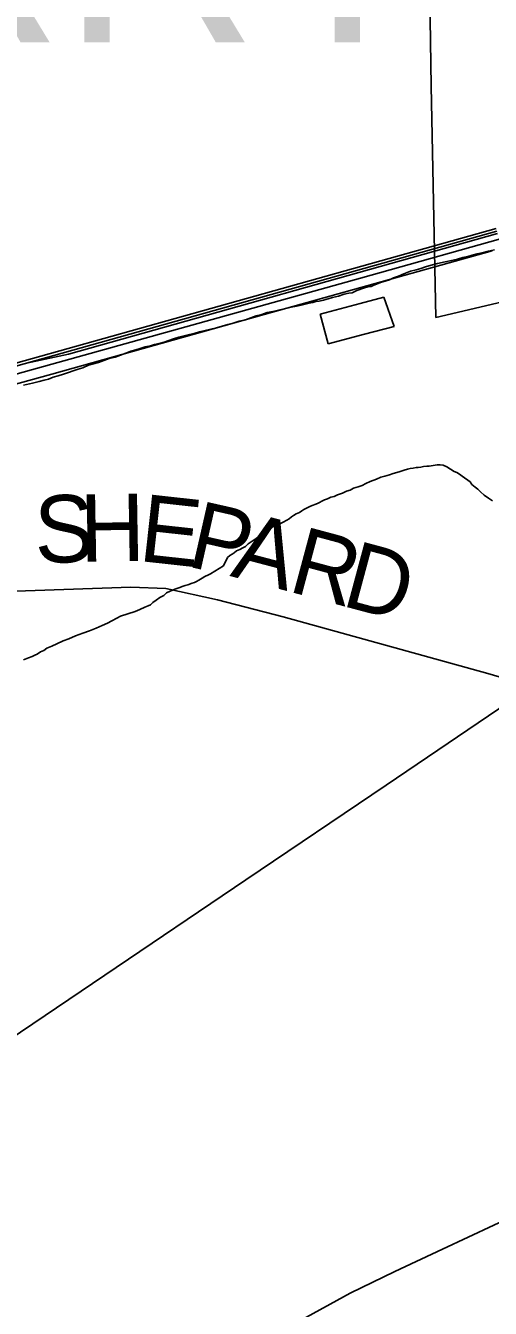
# Model space of a CAD drawing. Extents: x -59 to 82, y -3 to 49.
# Drawn here: x -49.098 to -48.706, y 47.357 to 48.44 of the extents above; entities that cross this region are included whole.
import ezdxf

# ---------------------------------------------------------------- set-up
doc = ezdxf.new("R2010")
doc.units = 0
for name, color, linetype in [('GM_X_Corporation', 7, 'Continuous'), ('GM_X_Minor_Lake', 7, 'Continuous'), ('GM_X_Minor_River', 7, 'Continuous'), ('GM_X_Rail_Line', 7, 'Continuous'), ('GM_X_State_Route', 7, 'Continuous'), ('GM_X_Township_Road', 7, 'Continuous'), ('GM_X_Township_Road_Text', 7, 'Continuous'), ('GM_X_Township_Text', 7, 'Continuous')]:
    doc.layers.add(name, color=color, linetype=linetype)

msp = doc.modelspace()

# ---------------------------------------------------------------- linework, layer by layer
at = {"layer": 'GM_X_Corporation'}
for p, q in [((-48.7611, 48.7525), (-48.7557, 48.3888)), ((-48.7557, 48.3888), (-48.7519, 48.1936)), ((-48.7519, 48.1936), (-48.3129, 48.2967))]:
    msp.add_line(p, q, dxfattribs=at)
at = {"layer": 'GM_X_Minor_Lake'}
for p, q in [((-48.8158, 48.2054), (-48.8494, 48.1964)), ((-48.8494, 48.1964), (-48.8158, 48.2054)), ((-48.7956, 48.2108), (-48.8158, 48.2054)), ((-48.787, 48.1859), (-48.7956, 48.2108)), ((-48.8494, 48.1964), (-48.8428, 48.1714)), ((-48.8428, 48.1714), (-48.8494, 48.1964)), ((-48.8121, 48.1794), (-48.787, 48.1859)), ((-48.8428, 48.1714), (-48.8121, 48.1794)), ((-48.8121, 48.1794), (-48.8428, 48.1714))]:
    msp.add_line(p, q, dxfattribs=at)
at = {"layer": 'GM_X_Minor_River'}
for p, q in [((-48.725, 48.2449), (-48.7212, 48.2462)), ((-48.7212, 48.2462), (-48.717, 48.2474)), ((-48.717, 48.2474), (-48.7129, 48.2482)), ((-48.7129, 48.2482), (-48.7076, 48.2495)), ((-48.7076, 48.2495), (-48.7023, 48.2507)), ((-48.7686, 48.2338), (-48.7644, 48.235)), ((-48.7644, 48.235), (-48.7606, 48.2362)), ((-48.7606, 48.2362), (-48.7557, 48.2378)), ((-48.7557, 48.2378), (-48.7504, 48.2391)), ((-48.7504, 48.2391), (-48.744, 48.2404)), ((-48.744, 48.2404), (-48.7386, 48.2416)), ((-48.7386, 48.2416), (-48.7337, 48.2429)), ((-48.7337, 48.2429), (-48.7292, 48.2441)), ((-48.7292, 48.2441), (-48.725, 48.2449)), ((-48.7977, 48.2233), (-48.7947, 48.2241)), ((-48.7947, 48.2241), (-48.7909, 48.2253)), ((-48.7909, 48.2253), (-48.7875, 48.2269)), ((-48.7875, 48.2269), (-48.7833, 48.2285)), ((-48.7833, 48.2285), (-48.7788, 48.2305)), ((-48.7788, 48.2305), (-48.7731, 48.2325)), ((-48.7731, 48.2325), (-48.7686, 48.2338)), ((-48.8341, 48.2115), (-48.8291, 48.2132)), ((-48.8291, 48.2132), (-48.8253, 48.214)), ((-48.8253, 48.214), (-48.8223, 48.2144)), ((-48.8223, 48.2144), (-48.8185, 48.2164)), ((-48.8185, 48.2164), (-48.8129, 48.2184)), ((-48.8129, 48.2184), (-48.8083, 48.2197)), ((-48.8083, 48.2197), (-48.8064, 48.2197)), ((-48.8064, 48.2197), (-48.8041, 48.2209)), ((-48.8041, 48.2209), (-48.8019, 48.2217)), ((-48.8019, 48.2217), (-48.7977, 48.2233)), ((-48.8784, 48.2011), (-48.8739, 48.2023)), ((-48.8739, 48.2023), (-48.8693, 48.2032)), ((-48.8693, 48.2032), (-48.8655, 48.204)), ((-48.8655, 48.204), (-48.8621, 48.2049)), ((-48.8621, 48.2049), (-48.8587, 48.2057)), ((-48.8587, 48.2057), (-48.8557, 48.2061)), ((-48.8557, 48.2061), (-48.853, 48.207)), ((-48.853, 48.207), (-48.8504, 48.2074)), ((-48.8504, 48.2074), (-48.8466, 48.2082)), ((-48.8466, 48.2082), (-48.8447, 48.2087)), ((-48.8447, 48.2087), (-48.839, 48.2103)), ((-48.839, 48.2103), (-48.8341, 48.2115)), ((-48.9178, 48.1904), (-48.9125, 48.1917)), ((-48.9125, 48.1917), (-48.908, 48.1933)), ((-48.908, 48.1933), (-48.9035, 48.1949)), ((-48.9035, 48.1949), (-48.8985, 48.1961)), ((-48.8985, 48.1961), (-48.894, 48.1978)), ((-48.894, 48.1978), (-48.8879, 48.199)), ((-48.8879, 48.199), (-48.8834, 48.1999)), ((-48.8834, 48.1999), (-48.8784, 48.2011)), ((-48.9557, 48.1801), (-48.9512, 48.1814)), ((-48.9512, 48.1814), (-48.9368, 48.1847)), ((-48.9368, 48.1847), (-48.9322, 48.1863)), ((-48.9322, 48.1863), (-48.9273, 48.1876)), ((-48.9273, 48.1876), (-48.9228, 48.1888)), ((-48.9228, 48.1888), (-48.9178, 48.1904)), ((-48.9925, 48.1695), (-48.9891, 48.1707)), ((-48.9891, 48.1707), (-48.9853, 48.1716)), ((-48.9853, 48.1716), (-48.9811, 48.1728)), ((-48.9811, 48.1728), (-48.977, 48.174)), ((-48.977, 48.174), (-48.9732, 48.1756)), ((-48.9732, 48.1756), (-48.9686, 48.1768)), ((-48.9686, 48.1768), (-48.9641, 48.1781)), ((-48.9641, 48.1781), (-48.9595, 48.1793)), ((-48.9595, 48.1793), (-48.9557, 48.1801)), ((-49.0319, 48.1573), (-49.0273, 48.1589)), ((-49.0273, 48.1589), (-49.0224, 48.1601)), ((-49.0224, 48.1601), (-49.0179, 48.1618)), ((-49.0179, 48.1618), (-49.0133, 48.1634)), ((-49.0133, 48.1634), (-49.0092, 48.165)), ((-49.0092, 48.165), (-49.005, 48.1662)), ((-49.005, 48.1662), (-49.0012, 48.1674)), ((-49.0012, 48.1674), (-48.997, 48.1687)), ((-48.997, 48.1687), (-48.9925, 48.1695)), ((-49.0618, 48.1472), (-49.0576, 48.1484)), ((-49.0576, 48.1484), (-49.0534, 48.15)), ((-49.0534, 48.15), (-49.0497, 48.1512)), ((-49.0497, 48.1512), (-49.0447, 48.1532)), ((-49.0447, 48.1532), (-49.0406, 48.1545)), ((-49.0406, 48.1545), (-49.0364, 48.1557)), ((-49.0364, 48.1557), (-49.0319, 48.1573)), ((-49.0997, 48.1365), (-49.0921, 48.1382)), ((-49.0921, 48.1382), (-49.0864, 48.1394)), ((-49.0864, 48.1394), (-49.0822, 48.1407)), ((-49.0822, 48.1407), (-49.0784, 48.1415)), ((-49.0784, 48.1415), (-49.0746, 48.1431)), ((-49.0746, 48.1431), (-49.0705, 48.1443)), ((-49.0705, 48.1443), (-49.0659, 48.1456)), ((-49.0659, 48.1456), (-49.0618, 48.1472)), ((-48.791, 48.0607), (-48.7879, 48.0619)), ((-48.7879, 48.0619), (-48.7849, 48.0627)), ((-48.7849, 48.0627), (-48.7819, 48.0636)), ((-48.7819, 48.0636), (-48.7785, 48.0648)), ((-48.7785, 48.0648), (-48.7758, 48.0656)), ((-48.7758, 48.0656), (-48.7736, 48.066)), ((-48.7736, 48.066), (-48.7709, 48.0664)), ((-48.7709, 48.0664), (-48.7686, 48.0669)), ((-48.7686, 48.0669), (-48.7667, 48.0669)), ((-48.7667, 48.0669), (-48.7644, 48.0673)), ((-48.7644, 48.0673), (-48.7622, 48.0678)), ((-48.7622, 48.0678), (-48.7595, 48.0682)), ((-48.7595, 48.0682), (-48.7576, 48.0682)), ((-48.7576, 48.0682), (-48.7542, 48.0687)), ((-48.7542, 48.0687), (-48.7508, 48.0691)), ((-48.7508, 48.0691), (-48.7481, 48.0692)), ((-48.7481, 48.0692), (-48.7458, 48.0689)), ((-48.7458, 48.0689), (-48.7427, 48.0674)), ((-48.7427, 48.0674), (-48.7396, 48.0656)), ((-48.7396, 48.0656), (-48.7365, 48.0637)), ((-48.7365, 48.0637), (-48.7342, 48.0626)), ((-48.7342, 48.0626), (-48.7319, 48.0612)), ((-48.8212, 48.0494), (-48.8174, 48.0507)), ((-48.8174, 48.0507), (-48.814, 48.0519)), ((-48.814, 48.0519), (-48.811, 48.0535)), ((-48.811, 48.0535), (-48.8072, 48.0551)), ((-48.8072, 48.0551), (-48.8019, 48.0571)), ((-48.8019, 48.0571), (-48.7982, 48.0587)), ((-48.7982, 48.0587), (-48.7948, 48.0595)), ((-48.7948, 48.0595), (-48.791, 48.0607)), ((-48.7319, 48.0612), (-48.7296, 48.0597)), ((-48.7296, 48.0597), (-48.723, 48.0549)), ((-48.723, 48.0549), (-48.7215, 48.0526)), ((-48.7215, 48.0526), (-48.7187, 48.0504)), ((-48.8481, 48.0386), (-48.8458, 48.0398)), ((-48.8458, 48.0398), (-48.8431, 48.0406)), ((-48.8431, 48.0406), (-48.8405, 48.0418)), ((-48.8405, 48.0418), (-48.8375, 48.0426)), ((-48.8375, 48.0426), (-48.8348, 48.0438)), ((-48.8348, 48.0438), (-48.8307, 48.0454)), ((-48.8307, 48.0454), (-48.8273, 48.047)), ((-48.8273, 48.047), (-48.8242, 48.0479)), ((-48.8242, 48.0479), (-48.8212, 48.0494)), ((-48.7187, 48.0504), (-48.7164, 48.0486)), ((-48.7164, 48.0486), (-48.7141, 48.0463)), ((-48.7141, 48.0463), (-48.711, 48.0437)), ((-48.711, 48.0437), (-48.7075, 48.0411)), ((-48.7075, 48.0411), (-48.704, 48.0389)), ((-48.8696, 48.0279), (-48.8669, 48.0291)), ((-48.8669, 48.0291), (-48.865, 48.0303)), ((-48.865, 48.0303), (-48.8632, 48.0315)), ((-48.8632, 48.0315), (-48.8598, 48.0331)), ((-48.8598, 48.0331), (-48.8575, 48.0343)), ((-48.8575, 48.0343), (-48.8518, 48.0367)), ((-48.8518, 48.0367), (-48.8499, 48.0375)), ((-48.8499, 48.0375), (-48.8481, 48.0386)), ((-48.8892, 48.0169), (-48.8846, 48.0189)), ((-48.8846, 48.0189), (-48.8805, 48.0209)), ((-48.8805, 48.0209), (-48.8775, 48.0224)), ((-48.8775, 48.0224), (-48.8756, 48.0236)), ((-48.8756, 48.0236), (-48.8737, 48.0252)), ((-48.8737, 48.0252), (-48.8718, 48.0264)), ((-48.8718, 48.0264), (-48.8696, 48.0279)), ((-48.9046, 48.0063), (-48.9023, 48.0079)), ((-48.9023, 48.0079), (-48.9001, 48.0094)), ((-48.9001, 48.0094), (-48.8963, 48.0122)), ((-48.8963, 48.0122), (-48.894, 48.0137)), ((-48.894, 48.0137), (-48.8914, 48.0149)), ((-48.8914, 48.0149), (-48.8892, 48.0169)), ((-48.9219, 47.9949), (-48.92, 47.9965)), ((-48.92, 47.9965), (-48.9173, 47.9977)), ((-48.9173, 47.9977), (-48.9147, 47.9992)), ((-48.9147, 47.9992), (-48.9124, 48.0004)), ((-48.9124, 48.0004), (-48.9102, 48.0024)), ((-48.9102, 48.0024), (-48.9076, 48.0043)), ((-48.9076, 48.0043), (-48.9046, 48.0063)), ((-48.9309, 47.984), (-48.9275, 47.991)), ((-48.9275, 47.991), (-48.9256, 47.9926)), ((-48.9256, 47.9926), (-48.9237, 47.9937)), ((-48.9237, 47.9937), (-48.9219, 47.9949)), ((-48.949, 47.9735), (-48.9468, 47.975)), ((-48.9468, 47.975), (-48.9437, 47.9765)), ((-48.9437, 47.9765), (-48.9418, 47.9773)), ((-48.9418, 47.9773), (-48.9309, 47.984)), ((-48.974, 47.9634), (-48.9721, 47.9642)), ((-48.9721, 47.9642), (-48.9702, 47.9649)), ((-48.9702, 47.9649), (-48.9679, 47.9657)), ((-48.9679, 47.9657), (-48.9657, 47.9665)), ((-48.9657, 47.9665), (-48.9634, 47.9673)), ((-48.9634, 47.9673), (-48.9611, 47.968)), ((-48.9611, 47.968), (-48.9573, 47.9692)), ((-48.9573, 47.9692), (-48.9554, 47.97)), ((-48.9554, 47.97), (-48.9536, 47.9708)), ((-48.9536, 47.9708), (-48.9517, 47.9719)), ((-48.9517, 47.9719), (-48.949, 47.9735)), ((-48.9906, 47.953), (-48.9876, 47.9549)), ((-48.9876, 47.9549), (-48.9846, 47.9572)), ((-48.9846, 47.9572), (-48.9812, 47.9588)), ((-48.9812, 47.9588), (-48.9789, 47.9611)), ((-48.9789, 47.9611), (-48.9759, 47.9626)), ((-48.9759, 47.9626), (-48.974, 47.9634)), ((-49.0179, 47.9414), (-49.0054, 47.9453)), ((-49.0054, 47.9453), (-49.0016, 47.9472)), ((-49.0016, 47.9472), (-48.9974, 47.9492)), ((-48.9974, 47.9492), (-48.9944, 47.9503)), ((-48.9944, 47.9503), (-48.9925, 47.9511)), ((-48.9925, 47.9511), (-48.9906, 47.953)), ((-49.0383, 47.9314), (-49.0334, 47.9337)), ((-49.0334, 47.9337), (-49.0288, 47.9356)), ((-49.0288, 47.9356), (-49.0251, 47.9376)), ((-49.0251, 47.9376), (-49.0209, 47.9399)), ((-49.0209, 47.9399), (-49.0179, 47.9414)), ((-49.0663, 47.9206), (-49.0614, 47.9225)), ((-49.0614, 47.9225), (-49.0557, 47.9248)), ((-49.0557, 47.9248), (-49.0497, 47.9271)), ((-49.0497, 47.9271), (-49.044, 47.9291)), ((-49.044, 47.9291), (-49.0383, 47.9314)), ((-49.0882, 47.9094), (-49.0852, 47.9113)), ((-49.0852, 47.9113), (-49.0826, 47.9125)), ((-49.0826, 47.9125), (-49.0799, 47.9144)), ((-49.0799, 47.9144), (-49.0758, 47.9163)), ((-49.0758, 47.9163), (-49.0716, 47.9182)), ((-49.0716, 47.9182), (-49.0663, 47.9206)), ((-49.0996, 47.9047), (-49.0954, 47.9063)), ((-49.0954, 47.9063), (-49.0924, 47.9074)), ((-49.0924, 47.9074), (-49.0901, 47.9086)), ((-49.0901, 47.9086), (-49.0882, 47.9094))]:
    msp.add_line(p, q, dxfattribs=at)
at = {"layer": 'GM_X_Rail_Line'}
for p, q in [((-48.5526, 48.3007), (-48.8153, 48.2266)), ((-49.1233, 48.1501), (-48.7011, 48.2687)), ((-49.1227, 48.1479), (-48.7005, 48.2665)), ((-49.0618, 48.1626), (-48.6999, 48.2643)), ((-48.8966, 48.196), (-48.7043, 48.2499)), ((-48.8153, 48.2266), (-49.734, 47.9711)), ((-49.0757, 48.1458), (-48.8966, 48.196)), ((-49.097, 48.1551), (-49.0618, 48.1626)), ((-49.1198, 48.1337), (-49.0757, 48.1458)), ((-48.7938, 47.7988), (-48.5069, 47.9935)), ((-48.9121, 47.7189), (-48.7938, 47.7988)), ((-49.0311, 47.6386), (-48.9121, 47.7189)), ((-49.2234, 47.5085), (-49.0311, 47.6386))]:
    msp.add_line(p, q, dxfattribs=at)
at = {"layer": 'GM_X_State_Route'}
for p, q in [((-48.7462, 47.4073), (-48.6518, 47.4514)), ((-48.7865, 47.3884), (-48.7462, 47.4073)), ((-48.824, 47.3701), (-48.7865, 47.3884)), ((-48.8666, 47.3467), (-48.824, 47.3701))]:
    msp.add_line(p, q, dxfattribs=at)
at = {"layer": 'GM_X_Township_Road'}
for p, q in [((-49.5322, 47.948), (-49.009, 47.966)), ((-49.009, 47.966), (-48.9795, 47.9649)), ((-48.9795, 47.9649), (-48.9361, 47.9553)), ((-48.9361, 47.9553), (-48.8806, 47.941)), ((-48.8806, 47.941), (-48.7081, 47.8932)), ((-48.7081, 47.8932), (-48.6282, 47.8693))]:
    msp.add_line(p, q, dxfattribs=at)

# ---------------------------------------------------------------- texts
at = {"layer": 'GM_X_Township_Road_Text'}
for s, rotation, p in [('S', 1.7725, (-49.0897, 47.9861)), ('H', 0.9763, (-49.0516, 47.9873)), ('E', 353.7261, (-49.0035, 47.9882)), ('P', 347.2073, (-48.963, 47.9838)), ('A', 345.2631, (-48.9261, 47.9755)), ('R', 344.9773, (-48.8778, 47.9628)), ('D', 344.9801, (-48.8327, 47.9507))]:
    msp.add_text(s, height=0.0568, rotation=rotation, dxfattribs=at).set_placement(p)
at = {"layer": 'GM_X_Township_Text'}
msp.add_text('PERRY', height=0.17045, rotation=0, dxfattribs=at).set_placement((-49.5357, 48.4258))

doc.saveas('drawing.dxf')
